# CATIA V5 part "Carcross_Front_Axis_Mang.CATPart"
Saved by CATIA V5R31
Part number: Carcross_Front_Axis_HP
Bounding box of the stored display mesh (mm): x -9953268 to 9953268, y -800 to 8345.383, z -966731.375 to 966808.75
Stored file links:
  R:\Din II\Pfinal\CAD\Carcross_Front_Axis.CATPart
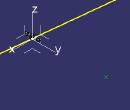
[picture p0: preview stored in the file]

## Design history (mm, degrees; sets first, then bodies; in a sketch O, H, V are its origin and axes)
AxisSystem1: origin (0, 0, 0), X (1, 0, 0), Y (0, 1, 0), Z (0, 0, 1)
Set1 "Front_Axis"
  Set2 "Left_wheel"
    Set3 "Lower_arm"
      Set4 "Lower_arm_C"
        Point1 "A": (-20, -57, 128.5), in AxisSystem1
        Point2 "B": (-18, -595, 108.5), in AxisSystem1
        Point3 "C": (211, -58, 135.5), in AxisSystem1
        Line1: type PtPt, FirstPoint Point1, SecondPoint Point2
        Line2: type PtPt, FirstPoint Point3, SecondPoint Point2
        Plane1 "Lower_plane": type 3Points, Element1 Point1, Element2 Point2, Element3 Point3
      Join1 "Lower_arm": Elements (Line1; Line2)
    Set5 "Upper_arm"
      Set6 "Upper_arm_C"
        Point4 "D": (-166, -99, 323.5), in AxisSystem1
        Point5 "E": (17, -546, 298.5), in AxisSystem1
        Point6 "F": (158, -124, 291.5), in AxisSystem1
        Line3: type PtPt, FirstPoint Point4, SecondPoint Point5
        Line4: type PtPt, FirstPoint Point6, SecondPoint Point5
        Plane2 "Upper_plane": type 3Points, Element1 Point4, Element2 Point5, Element3 Point6
      Join2 "Upper_arm": Elements (Line3; Line4)
    Set7 "IC_RollCenter"
      Intersect1 "IC_Line": ToIntersect1 Plane1, ToIntersect2 Plane2
      Intersect2 "IC_point_YZ": ToIntersect1 YZ plane of AxisSystem1, ToIntersect2 Intersect1
      Line5: type PtPt, FirstPoint Intersect5, SecondPoint Intersect2
      Intersect3 "RollCenter": ToIntersect1 ZX plane of AxisSystem1, ToIntersect2 Plane3
      Project1 "Tierod_Projection": ToProject Join3, Support YZ plane of AxisSystem1
      Intersect4 "IC_Aux_ZX": ToIntersect1 Intersect1, ToIntersect2 ZX plane of AxisSystem1
      Plane3 "IC_Plane": type 1Line1Pt, RefPoint Intersect5, Line Intersect1
      Line6 "Tie_rod_IC": type Tangency, RefPoint vertex of Project1, Curve Project1, Start 0, End 8452.795
    Set8 "tie_rod"
      Set9 "tie_rod_C"
        Point7 "In": (-64, -105, 240.5), in AxisSystem1
        Point8 "Out": (-78, -588, 230), in AxisSystem1
        Line7: type PtPt, FirstPoint Point7, SecondPoint Point8
      Join3 "tierod": Elements Line7
    Set10 "Strut"
      Set11 "Strut_C"
        Point9 "Down": (3, -520, 148.5), in AxisSystem1
        Point10 "Up": (39, -166, 383.5), in AxisSystem1
        Line8: type PtPt, FirstPoint Point9, SecondPoint Point10
      Join4 "Strut": Elements Line8
    Set12 "Wheel"
      Point11 "Wheel_Center": (0, -800, 242.5), in AxisSystem1
      Line9: type PtDir, RefPoint Point11, Direction (0, 0, 1), Start -400, End 400
      Intersect5 "Wheel_Floor": ToIntersect1 Line9, ToIntersect2 XY plane of AxisSystem1
    Set13 "Mangeta"
      Set14 "Mangeta_C"
        Line10: type PtPt, FirstPoint Point2, SecondPoint Point11
        Line11: type PtPt, FirstPoint Point8, SecondPoint Point11
        Line12: type PtPt, FirstPoint Point5, SecondPoint Point11
  Set15 "Right_Wheel"
    MultiSel1
Body1 (main body)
